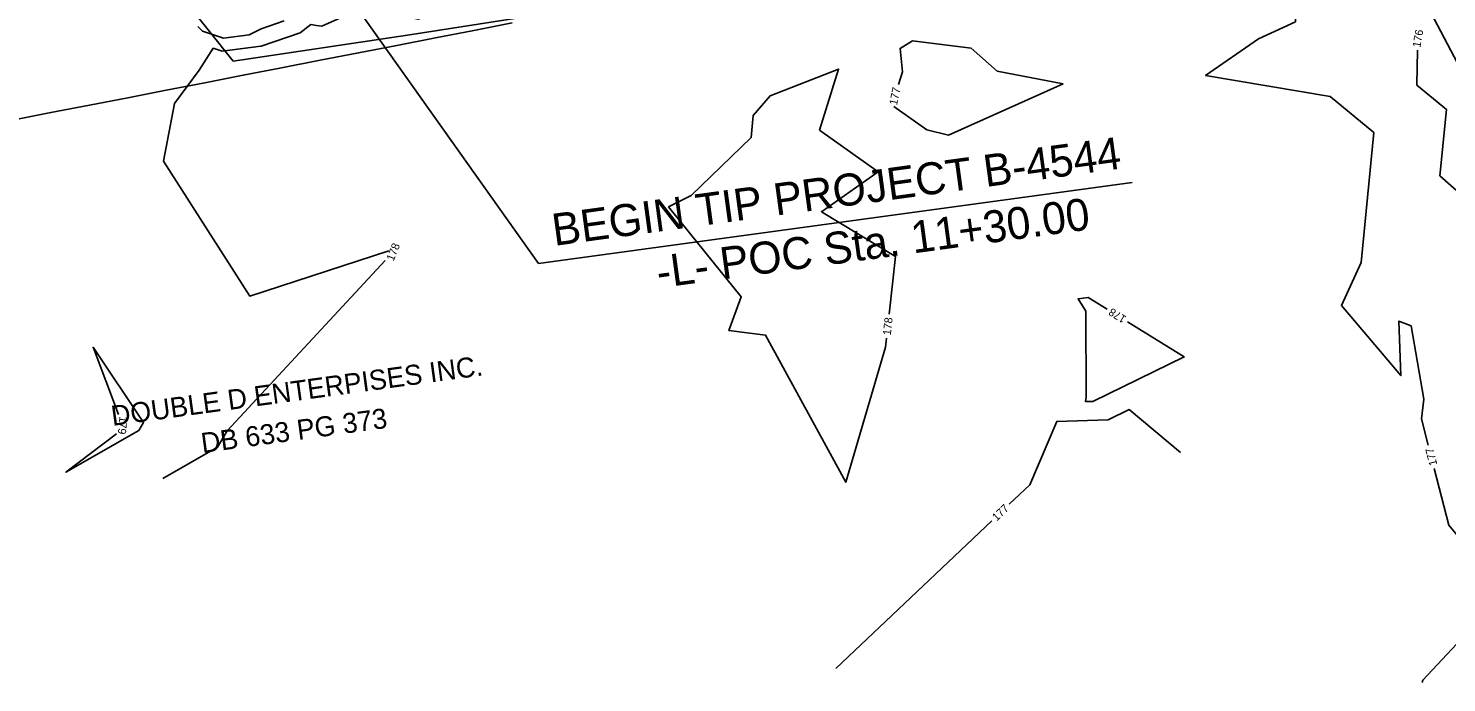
# Model space of a CAD drawing. Extents: x 2086416 to 2115205, y 575507 to 632762.
# Drawn here: x 2111202.3 to 2111556.7, y 581407.4 to 581570.9 of the extents above; entities that cross this region are included whole.
import ezdxf

# ---------------------------------------------------------------- set-up
doc = ezdxf.new("R2010")
doc.units = 0
for name, color, linetype in [('DTM Contours Minor', 7, 'Continuous'), ('DTM Contours Minor Text', 7, 'Continuous'), ('Exist Hydrographic FEMA Cross Section', 7, 'Continuous'), ('Exist Property Deed Book Text', 7, 'Continuous'), ('Exist Property Owner Text', 7, 'Continuous'), ('Exist Vegetation Woods Line', 7, 'Continuous'), ('Prop Horizontal Alignment Station Label', 7, 'Continuous')]:
    doc.layers.add(name, color=color, linetype=linetype)

msp = doc.modelspace()

# ---------------------------------------------------------------- linework, layer by layer
at = {"layer": 'DTM Contours Minor'}
for points in [[(2111320.44, 581578.03), (2111318.46, 581578.24), (2111315.74, 581578.08), (2111307.71, 581576.17), (2111299.75, 581573.25), (2111295.09, 581574.15), (2111288.19, 581576.48), (2111288.82, 581585.08), (2111287.21, 581576.68), (2111275.7, 581571.5), (2111274.31, 581571.68), (2111272.9, 581571.92), (2111270.27, 581569.85), (2111260.49, 581566.51), (2111260.44, 581566.49), (2111250.75, 581565.23), (2111248.56, 581565.97), (2111245.06, 581560.52), (2111238.88, 581552.13), (2111236.15, 581537.73), (2111257.66, 581504.04), (2111292.42, 581515.32)], [(2111514.58, 581584.29), (2111519.19, 581578.84), (2111518.93, 581572.6), (2111509.75, 581568.35), (2111496.49, 581559.18), (2111527.62, 581553.93), (2111538.57, 581544.91), (2111535.36, 581512.4), (2111530.44, 581501.65), (2111545.28, 581484.15), (2111544.79, 581497.77), (2111547.82, 581496.57), (2111551.06, 581478.3), (2111550.44, 581473.33), (2111552.13, 581466.8)], [(2111266.29, 581572.81), (2111260.51, 581570.84), (2111257.48, 581569.31), (2111251.06, 581568.48), (2111245.89, 581570.23), (2111244.7, 581571.41)], [(2111460.9, 581557.08), (2111444.39, 581560.24), (2111437.91, 581565.95), (2111423.3, 581567.8), (2111420.16, 581565.92), (2111420.73, 581560.08), (2111419.75, 581556.92)], [(2111549.42, 581565.48), (2111549.3, 581556.75), (2111556.68, 581550.67), (2111555.04, 581534.11), (2111575.11, 581516.45), (2111580.14, 581502.39), (2111580.74, 581501.15), (2111583.03, 581497), (2111577.68, 581466.9), (2111605.74, 581475), (2111607.43, 581474.14), (2111607.69, 581473.21), (2111591.9, 581421.84), (2111590.92, 581419.37), (2111591.04, 581419.17), (2111590.97, 581419.11)], [(2111400.04, 581545.48), (2111404.78, 581560.74), (2111387.67, 581554.07), (2111383.48, 581549.16), (2111382.97, 581543.66), (2111367.99, 581529.18), (2111362.31, 581526.33), (2111380.49, 581503.83), (2111377.38, 581495.42), (2111386.55, 581494.27), (2111406.58, 581457.51), (2111416.51, 581491.31), (2111416.75, 581493.56)], [(2111418.62, 581551.41), (2111426.83, 581545.6), (2111432.28, 581544.28), (2111460.9, 581557.08)], [(2111417.41, 581499.52), (2111418.98, 581513.93), (2111400.52, 581525.12), (2111414.71, 581535.1), (2111400.04, 581545.48)], [(2111291.46, 581512.92), (2111252.01, 581470.38), (2111249.64, 581466.25), (2111235.98, 581458.44)], [(2111471.86, 581500.76), (2111467.18, 581503.65), (2111464.64, 581503.37), (2111466.57, 581500.29), (2111466.66, 581478.81), (2111466.52, 581477.67), (2111468.3, 581477.73)], [(2111468.3, 581477.73), (2111491.15, 581488.83), (2111476.96, 581497.6)], [(2111229.93, 581470.42), (2111231.08, 581472.42), (2111218.5, 581491.24), (2111224.84, 581474.47)], [(2111490.22, 581464.95), (2111477.4, 581475.68), (2111472.18, 581473.14), (2111459.31, 581472.7), (2111452.54, 581456.87), (2111447.42, 581452.02)], [(2111224.39, 581469.6), (2111211.72, 581460.01), (2111229.93, 581470.42)], [(2111553.63, 581460.99), (2111557.31, 581446.76), (2111571.28, 581429.98), (2111550.77, 581408.08), (2111550.64, 581407.44)], [(2111443.07, 581447.89), (2111404.11, 581410.98)]]:
    msp.add_lwpolyline(points, dxfattribs=at)
at = {"layer": 'Exist Hydrographic FEMA Cross Section'}
msp.add_lwpolyline([(2111323.27, 581572.29), (2111313.66, 581570.42), (2111304.05, 581568.55), (2111294.44, 581566.69), (2111284.84, 581564.82), (2111275.23, 581562.95), (2111265.62, 581561.08), (2111256.02, 581559.21), (2111246.41, 581557.34), (2111236.8, 581555.48), (2111227.19, 581553.61), (2111217.58, 581551.74), (2111207.98, 581549.87), (2111198.37, 581548)], dxfattribs=at)
at = {"layer": 'Exist Vegetation Woods Line'}
msp.add_lwpolyline([(2111566.76, 581548.29), (2111551.99, 581576.31), (2111385.4, 581583.05), (2111297.09, 581569.27), (2111253.55, 581562.72), (2111242.01, 581577.17), (2111257.87, 581581.4)], dxfattribs=at)
at = {"layer": 'Prop Horizontal Alignment Station Label'}
for p, q in [((2111329.83, 581512.18), (2111252.58, 581621.04)), ((2111478.14, 581532.42), (2111329.83, 581512.18))]:
    msp.add_line(p, q, dxfattribs=at)

# ---------------------------------------------------------------- texts
at = {"layer": 'DTM Contours Minor Text'}
for s, rotation, p in [('176', 80.2052, (2111550.15, 581566.05)), ('177', 78.4527, (2111419.38, 581551.62)), ('178', 68.2246, (2111293.59, 581512.63)), ('178', 148.264, (2111476.87, 581498.83)), ('178', 83.7635, (2111417.83, 581494.17)), ('179', 264.7198, (2111225.12, 581474.03)), ('177', 104.5019, (2111554.42, 581461.94)), ('177', 43.4551, (2111444.28, 581447.67))]:
    msp.add_text(s, height=2, rotation=rotation, dxfattribs=at).set_placement(p)
at = {"layer": 'Exist Property Deed Book Text'}
msp.add_text('DB 633 PG 373', height=5, rotation=7.771, dxfattribs=at).set_placement((2111245.85, 581464.8))
at = {"layer": 'Exist Property Owner Text'}
msp.add_text('DOUBLE D ENTERPISES INC.', height=5, rotation=7.771, dxfattribs=at).set_placement((2111223.38, 581471.59))
at = {"layer": 'Prop Horizontal Alignment Station Label'}
for s, p in [('BEGIN TIP PROJECT B-4544', (2111333.76, 581516.57)), ('-L- POC Sta. 11+30.00', (2111359.83, 581506))]:
    msp.add_text(s, height=8, rotation=7.771, dxfattribs=at).set_placement(p)

doc.saveas('drawing.dxf')
